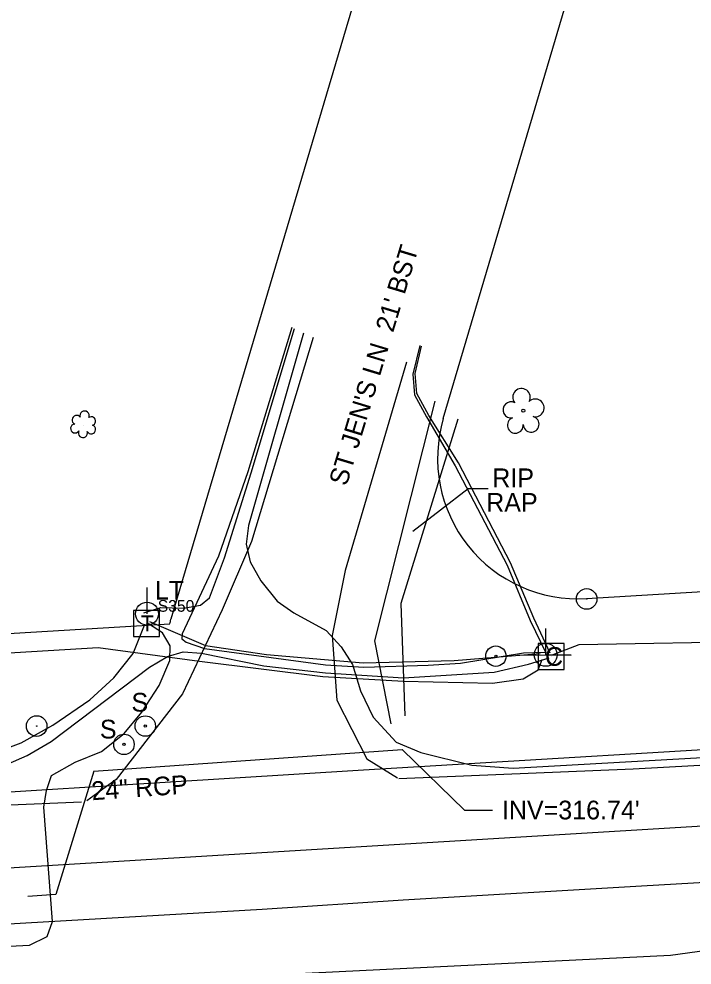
# Model space of a CAD drawing. Extents: x 2110969 to 2113691, y 670003 to 672285.
# Drawn here: x 2112343.6 to 2112487.4, y 670466.5 to 670668.7 of the extents above; entities that cross this region are included whole.
import ezdxf

# ---------------------------------------------------------------- set-up
doc = ezdxf.new("R2010")
doc.units = 0
for name, color, linetype in [('Default', 7, 'Continuous'), ('Exist Horizontal Alignment', 7, 'Continuous'), ('Exist Other Culture Anchor (Guy Wire) CELL', 7, 'Continuous'), ('Exist Other Culture Area Outline', 7, 'Continuous'), ('Exist Other Culture Area Outline Leader', 7, 'Continuous'), ('Exist Other Culture Area Outline Text', 7, 'Continuous'), ('Exist Other Culture Sign Text', 7, 'Continuous'), ('Exist Property Iron Pin CELL', 7, 'Continuous'), ('Exist Right of Way Line', 7, 'Continuous'), ('Exist Right of Way Symbol CELL', 7, 'Continuous'), ('Exist Roads EOP', 7, 'Continuous'), ('Exist Roads EOP Text', 7, 'Continuous'), ('Exist Structure Minor Pipes RCP 24 Inch', 7, 'Continuous'), ('Exist Structure Minor Pipes RCP 24 Inch Invert', 7, 'Continuous'), ('Exist Structure Minor Pipes RCP 24 Inch Leader', 7, 'Continuous'), ('Exist Structure Minor Pipes RCP 24 Inch Text', 7, 'Continuous'), ('Exist Utilities Power Joint Use Telephone CELL', 7, 'Continuous'), ('Exist Utilities Power Pole CELL', 7, 'Continuous'), ('Exist Utilities Power Pole Text', 7, 'Continuous'), ('Exist Utilities Power UG Cable SUE LOS B', 7, 'Continuous'), ('Exist Utilities Telephone Pedestal CELL', 7, 'Continuous'), ('Exist Utilities Telephone Pedestal Cogo Number', 7, 'Continuous'), ('Exist Utilities Telephone UG Cable SUE LOS B', 7, 'Continuous'), ('Exist Utilities Telephone UG FO SUE LOS B', 7, 'Continuous'), ('Exist Utilities TV Pedestal CELL', 7, 'Continuous'), ('Exist Utilities TV UG Cable SUE LOS B', 7, 'Continuous'), ('Exist Utilities TV UG FO Cable SUE LOS B', 7, 'Continuous'), ('Exist Utilities Water UG Line SUE LOS B', 7, 'Continuous'), ('Exist Vegetation Shrub CELL', 7, 'Continuous'), ('Exist Vegetation Tree CELL', 7, 'Continuous')]:
    doc.layers.add(name, color=color, linetype=linetype)

msp = doc.modelspace()

# ---------------------------------------------------------------- linework, layer by layer
at = {"layer": 'Default'}
for centre, radius in [((2112370.63, 670517.59), 2.18), ((2112366.07, 670513.67), 2.18), ((2112370.63, 670517.59), 0.24), ((2112366.07, 670513.67), 0.24)]:
    msp.add_circle(centre, radius, dxfattribs=at)
at = {"layer": 'Exist Horizontal Alignment'}
msp.add_line((2111597.13, 670442.15), (2113362.13, 670549.12), dxfattribs=at)
at = {"layer": 'Exist Other Culture Anchor (Guy Wire) CELL'}
for radius in [2.18, 0.24]:
    msp.add_circle((2112445.52, 670532.52), radius, dxfattribs=at)
at = {"layer": 'Exist Other Culture Area Outline'}
for points in [[(2112423.12, 670518.08), (2112419.67, 670535.82), (2112432.56, 670586.99)], [(2112437.41, 670583.17), (2112425.19, 670543.74), (2112426.08, 670519.76)]]:
    msp.add_lwpolyline(points, dxfattribs=at)
at = {"layer": 'Exist Other Culture Area Outline Leader'}
msp.add_lwpolyline([(2112427.79, 670559.25), (2112439.58, 670568.31), (2112443.89, 670568.31)], dxfattribs=at)
at = {"layer": 'Exist Property Iron Pin CELL'}
for centre, radius in [((2112464.92, 670544.74), 2.2), ((2112464.92, 670544.74), 0.0707), ((2112347.42, 670517.58), 2.2), ((2112347.42, 670517.58), 2.2), ((2112347.42, 670517.58), 0.0707), ((2112347.42, 670517.58), 0.0707)]:
    msp.add_circle(centre, radius, dxfattribs=at)
at = {"layer": 'Exist Right of Way Line'}
for p, q in [((2112434.29, 670583.29), (2112486.67, 670760.31)), ((2112433.78, 670735.06), (2112376.09, 670540.39)), ((2112464.87, 670544.84), (2112636.48, 670555.24)), ((2112002.21, 670516.79), (2112375.84, 670539.44))]:
    msp.add_line(p, q, dxfattribs=at)
msp.add_arc((2112346.97, 670547.58), 30, 344.2535, 346.1413, dxfattribs=at)
at = {"layer": 'Exist Right of Way Symbol CELL'}
msp.add_arc((2112463.06, 670574.78), 30, 163.5164, 273.4682, dxfattribs=at)
at = {"layer": 'Exist Roads EOP'}
for points in [[(2112406.52, 670600.58), (2112393.34, 670557), (2112387.02, 670542.43), (2112378.59, 670524.48), (2112364.4, 670506.13), (2112358.11, 670501.61)], [(2112426.44, 670595.36), (2112413.3, 670550.81), (2112410.52, 670536.95), (2112411.52, 670523.08), (2112417.92, 670510.58), (2112424.52, 670506.54)], [(2112424.8, 670506.36), (2112474.87, 670508.43), (2112528, 670511.35), (2112576.77, 670514.15), (2112631.06, 670517.43), (2112688.93, 670521.02)], [(2112176.4, 670489.41), (2112242.12, 670493.63), (2112288.77, 670496.68), (2112321.51, 670499.72), (2112322.2, 670500.39), (2112339.25, 670501.32), (2112340.12, 670500.67), (2112356.98, 670501.39)], [(2112239.79, 670466.76), (2112249.04, 670469.51), (2112290.21, 670472.2), (2112340.18, 670475.23), (2112395.57, 670478.46), (2112425.73, 670480.47), (2112476.62, 670483.47), (2112528.49, 670486.45), (2112578.55, 670489.44), (2112632.17, 670492.66), (2112690.33, 670496.03), (2112733.41, 670498.51), (2112776.92, 670500.99)]]:
    msp.add_lwpolyline(points, dxfattribs=at)
at = {"layer": 'Exist Structure Minor Pipes RCP 24 Inch'}
msp.add_line((2112359.62, 670507.93), (2112425.48, 670512.56), dxfattribs=at)
at = {"layer": 'Exist Structure Minor Pipes RCP 24 Inch Leader'}
for points in [[(2112425.48, 670512.56), (2112438.81, 670499.64), (2112444.81, 670499.64)], [(2112359.62, 670507.93), (2112351.52, 670481.56), (2112345.53, 670481.19)]]:
    msp.add_lwpolyline(points, dxfattribs=at)
at = {"layer": 'Exist Utilities Power Joint Use Telephone CELL'}
msp.add_line((2112456.17, 670532.79), (2112456.17, 670532.79), dxfattribs=at)
msp.add_lwpolyline([(2112450.23, 670532.79), (2112461.57, 670532.75), (2112456.17, 670532.77), (2112456.17, 670538.41)], dxfattribs=at)
msp.add_circle((2112456.17, 670532.8), 2.45, dxfattribs=at)
at = {"layer": 'Exist Utilities Power Pole CELL'}
for q in [(2112370.99, 670547.22), (2112370.99, 670541.59)]:
    msp.add_line((2112370.99, 670541.59), q, dxfattribs=at)
msp.add_circle((2112370.99, 670541.59), 2.45, dxfattribs=at)
at = {"layer": 'Exist Utilities Power UG Cable SUE LOS B'}
for points in [[(2112370.34, 670541.77), (2112373.96, 670542.89), (2112378.76, 670542.74), (2112382.42, 670543.39), (2112384.33, 670545), (2112387.53, 670553.53), (2112393.23, 670571.68), (2112402.5, 670602.53)], [(2112370.34, 670541.77), (2112373.96, 670542.89), (2112378.76, 670542.74), (2112382.42, 670543.39), (2112384.33, 670545), (2112387.53, 670553.53), (2112393.23, 670571.68), (2112402.5, 670602.53)], [(2112401.94, 670602.73), (2112392.55, 670571.92), (2112386.23, 670553.9), (2112378.48, 670537.29), (2112378.4, 670536.19), (2112379.38, 670535.53), (2112383.28, 670534.17), (2112409.09, 670530.63), (2112417.28, 670530.14), (2112431.07, 670530.56), (2112437.99, 670530.99), (2112451.4, 670533.2), (2112455.98, 670533.35)], [(2112401.94, 670602.73), (2112392.55, 670571.92), (2112386.23, 670553.9), (2112378.48, 670537.29), (2112378.4, 670536.19), (2112379.38, 670535.53), (2112383.28, 670534.17), (2112409.09, 670530.63), (2112417.28, 670530.14), (2112431.07, 670530.56), (2112437.99, 670530.99), (2112451.4, 670533.2), (2112455.98, 670533.35)], [(2112429.25, 670598.93), (2112427.81, 670592.76), (2112428.12, 670588.34), (2112430.72, 670583.62), (2112436.81, 670573.15), (2112447.91, 670551.93), (2112452.85, 670540.14), (2112456.2, 670533.23)], [(2112429.25, 670598.93), (2112427.81, 670592.76), (2112428.12, 670588.34), (2112430.72, 670583.62), (2112436.81, 670573.15), (2112447.91, 670551.93), (2112452.85, 670540.14), (2112456.2, 670533.23)]]:
    msp.add_lwpolyline(points, dxfattribs=at)
at = {"layer": 'Exist Utilities Telephone Pedestal CELL'}
msp.add_line((2112370.79, 670539.51), (2112370.79, 670539.51), dxfattribs=at)
msp.add_line((2112370.79, 670539.51), (2112370.79, 670539.51), dxfattribs=at)
msp.add_lwpolyline([(2112368.07, 670536.69), (2112373.66, 670536.69), (2112373.66, 670542.28), (2112368.07, 670542.28), (2112368.07, 670536.69)], dxfattribs=at)
msp.add_lwpolyline([(2112368.07, 670536.69), (2112373.66, 670536.69), (2112373.66, 670542.28), (2112368.07, 670542.28), (2112368.07, 670536.69)], dxfattribs=at)
at = {"layer": 'Exist Utilities Telephone UG Cable SUE LOS B'}
for points in [[(2112404.42, 670601.5), (2112392.64, 670560.41), (2112392.2, 670556.46), (2112393.02, 670552.68), (2112395.3, 670548.58), (2112398.79, 670544.3), (2112402.34, 670541.77), (2112409.23, 670538.01), (2112412.45, 670534.52), (2112414.89, 670530.7), (2112416.63, 670525.08), (2112419.28, 670519.5), (2112424.23, 670514.15), (2112429.5, 670511.95), (2112440.36, 670509.2), (2112449.21, 670508.58), (2112498.52, 670511.36)], [(2112404.42, 670601.5), (2112392.64, 670560.41), (2112392.2, 670556.46), (2112393.02, 670552.68), (2112395.3, 670548.58), (2112398.79, 670544.3), (2112402.34, 670541.77), (2112409.23, 670538.01), (2112412.45, 670534.52), (2112414.89, 670530.7), (2112416.63, 670525.08), (2112419.28, 670519.5), (2112424.23, 670514.15), (2112429.5, 670511.95), (2112440.36, 670509.2), (2112449.21, 670508.58), (2112498.52, 670511.36)], [(2112125.8, 670505.88), (2112151.42, 670507.16), (2112167.82, 670506.07), (2112175.89, 670503.95), (2112185.08, 670501.15), (2112202.64, 670498.92), (2112224.06, 670500.86), (2112249.24, 670503.38), (2112272.81, 670505.79), (2112322.5, 670509.71), (2112334.68, 670510.5), (2112344.08, 670514.03), (2112350.84, 670517.78), (2112358.78, 670523.19), (2112363.87, 670527.87), (2112368.03, 670533.1), (2112370.46, 670539.12)], [(2112125.8, 670505.88), (2112151.42, 670507.16), (2112167.82, 670506.07), (2112175.89, 670503.95), (2112185.08, 670501.15), (2112202.64, 670498.92), (2112224.06, 670500.86), (2112249.24, 670503.38), (2112272.81, 670505.79), (2112322.5, 670509.71), (2112334.68, 670510.5), (2112344.08, 670514.03), (2112350.84, 670517.78), (2112358.78, 670523.19), (2112363.87, 670527.87), (2112368.03, 670533.1), (2112370.46, 670539.12)], [(2112269.39, 670466.11), (2112308.69, 670468.9), (2112345.88, 670470.75), (2112349.64, 670472.64), (2112350.81, 670475.84), (2112348.97, 670500.24), (2112349.51, 670503.8), (2112350.6, 670506.99), (2112355.66, 670509.89), (2112361.29, 670512.16), (2112366.08, 670515.96), (2112369.85, 670520.57), (2112373.6, 670526.25), (2112375.89, 670531.57), (2112375.94, 670534.69), (2112374.31, 670537.47), (2112371.32, 670539.46)], [(2112269.39, 670466.11), (2112308.69, 670468.9), (2112345.88, 670470.75), (2112349.64, 670472.64), (2112350.81, 670475.84), (2112348.97, 670500.24), (2112349.51, 670503.8), (2112350.6, 670506.99), (2112355.66, 670509.89), (2112361.29, 670512.16), (2112366.08, 670515.96), (2112369.85, 670520.57), (2112373.6, 670526.25), (2112375.89, 670531.57), (2112375.94, 670534.69), (2112374.31, 670537.47), (2112371.32, 670539.46)], [(2112371.52, 670539.93), (2112380.52, 670536.07), (2112383.49, 670534.77), (2112396.55, 670532.85), (2112417.17, 670531.11), (2112436.61, 670531.57), (2112454.98, 670533.12)], [(2112371.52, 670539.93), (2112380.52, 670536.07), (2112383.49, 670534.77), (2112396.55, 670532.85), (2112417.17, 670531.11), (2112436.61, 670531.57), (2112454.98, 670533.12)]]:
    msp.add_lwpolyline(points, dxfattribs=at)
at = {"layer": 'Exist Utilities Telephone UG FO SUE LOS B'}
msp.add_lwpolyline([(2111579.85, 670418.18), (2111631.45, 670423.41), (2111740.38, 670432.81), (2111885.62, 670444.53), (2111926.38, 670441.18), (2111977.11, 670441.9), (2112063.2, 670445.72), (2112109.68, 670453.08), (2112138.77, 670453.18), (2112237, 670457.87), (2112306.5, 670460.33), (2112380.27, 670463.6), (2112482.83, 670468.65), (2112529.94, 670475.11), (2112581.42, 670479.39), (2112613.55, 670486.14), (2112667.68, 670491.25), (2112816.71, 670501.11)], dxfattribs=at)
msp.add_lwpolyline([(2111579.85, 670418.18), (2111631.45, 670423.41), (2111740.38, 670432.81), (2111885.62, 670444.53), (2111926.38, 670441.18), (2111977.11, 670441.9), (2112063.2, 670445.72), (2112109.68, 670453.08), (2112138.77, 670453.18), (2112237, 670457.87), (2112306.5, 670460.33), (2112380.27, 670463.6), (2112482.83, 670468.65), (2112529.94, 670475.11), (2112581.42, 670479.39), (2112613.55, 670486.14), (2112667.68, 670491.25), (2112816.71, 670501.11)], dxfattribs=at)
at = {"layer": 'Exist Utilities TV Pedestal CELL'}
msp.add_line((2112457.32, 670532.45), (2112457.32, 670532.45), dxfattribs=at)
msp.add_line((2112457.32, 670532.45), (2112457.32, 670532.45), dxfattribs=at)
msp.add_lwpolyline([(2112454.54, 670529.68), (2112460.09, 670529.68), (2112460.09, 670535.23), (2112454.54, 670535.23), (2112454.54, 670529.68)], dxfattribs=at)
msp.add_lwpolyline([(2112454.54, 670529.68), (2112460.09, 670529.68), (2112460.09, 670535.23), (2112454.54, 670535.23), (2112454.54, 670529.68)], dxfattribs=at)
at = {"layer": 'Exist Utilities TV UG Cable SUE LOS B'}
for points in [[(2112457.14, 670533.15), (2112453.6, 670540.6), (2112448.62, 670552.49), (2112437.56, 670573.8), (2112431.2, 670583.96), (2112428.63, 670588.61), (2112428.28, 670592.91), (2112429.65, 670598.77)], [(2112457.14, 670533.15), (2112453.6, 670540.6), (2112448.62, 670552.49), (2112437.56, 670573.8), (2112431.2, 670583.96), (2112428.63, 670588.61), (2112428.28, 670592.91), (2112429.65, 670598.77)], [(2112457.79, 670532.84), (2112463.34, 670534.99), (2112503.28, 670535.72), (2112536.36, 670537.77), (2112607.48, 670541.98), (2112636.29, 670544.75), (2112653.86, 670545.32), (2112661.64, 670544.86)], [(2112457.79, 670532.84), (2112463.34, 670534.99), (2112503.28, 670535.72), (2112536.36, 670537.77), (2112607.48, 670541.98), (2112636.29, 670544.75), (2112653.86, 670545.32), (2112661.64, 670544.86)], [(2112188.85, 670513.35), (2112191.54, 670508.61), (2112194.04, 670505.15), (2112197.61, 670502.68), (2112202.27, 670501.48), (2112208.12, 670501.36), (2112249.19, 670503.68), (2112272.77, 670504.74), (2112322.55, 670508.19), (2112335.1, 670508.45), (2112341.36, 670509.49), (2112345.38, 670511.27), (2112350.51, 670514.31), (2112371.55, 670530.16), (2112375.39, 670532.48), (2112378.7, 670533.44), (2112382.64, 670533.13), (2112395.98, 670530.48), (2112409.14, 670528.93), (2112425.81, 670527.86), (2112445.18, 670529.08), (2112452.46, 670530.8), (2112456.91, 670532.18)], [(2112188.85, 670513.35), (2112191.54, 670508.61), (2112194.04, 670505.15), (2112197.61, 670502.68), (2112202.27, 670501.48), (2112208.12, 670501.36), (2112249.19, 670503.68), (2112272.77, 670504.74), (2112322.55, 670508.19), (2112335.1, 670508.45), (2112341.36, 670509.49), (2112345.38, 670511.27), (2112350.51, 670514.31), (2112371.55, 670530.16), (2112375.39, 670532.48), (2112378.7, 670533.44), (2112382.64, 670533.13), (2112395.98, 670530.48), (2112409.14, 670528.93), (2112425.81, 670527.86), (2112445.18, 670529.08), (2112452.46, 670530.8), (2112456.91, 670532.18)]]:
    msp.add_lwpolyline(points, dxfattribs=at)
at = {"layer": 'Exist Utilities TV UG FO Cable SUE LOS B'}
msp.add_lwpolyline([(2111936.85, 670495.19), (2111942.8, 670493.29), (2111948.9, 670492.04), (2111960.42, 670490.85), (2111972.12, 670490.75), (2111991.92, 670492.74), (2112005.47, 670495.02), (2112045.67, 670498.63), (2112084.03, 670500.97), (2112127.19, 670501.84), (2112167.43, 670504.61), (2112208.93, 670510.16), (2112249.37, 670516.92), (2112286.91, 670525.52), (2112332.02, 670532.67), (2112360.55, 670534.37), (2112382.17, 670531.42), (2112408.52, 670528.19), (2112425.77, 670527.19), (2112444.78, 670526.78), (2112451.38, 670527.68), (2112454.55, 670529.63), (2112455.41, 670531.77)], dxfattribs=at)
msp.add_lwpolyline([(2111936.85, 670495.19), (2111942.8, 670493.29), (2111948.9, 670492.04), (2111960.42, 670490.85), (2111972.12, 670490.75), (2111991.92, 670492.74), (2112005.47, 670495.02), (2112045.67, 670498.63), (2112084.03, 670500.97), (2112127.19, 670501.84), (2112167.43, 670504.61), (2112208.93, 670510.16), (2112249.37, 670516.92), (2112286.91, 670525.52), (2112332.02, 670532.67), (2112360.55, 670534.37), (2112382.17, 670531.42), (2112408.52, 670528.19), (2112425.77, 670527.19), (2112444.78, 670526.78), (2112451.38, 670527.68), (2112454.55, 670529.63), (2112455.41, 670531.77)], dxfattribs=at)
at = {"layer": 'Exist Utilities Water UG Line SUE LOS B'}
msp.add_lwpolyline([(2112063.12, 670452.82), (2112061.08, 670490.25), (2112149, 670492.87), (2112291.17, 670500.39), (2112417.24, 670508.2), (2112519.46, 670514.32), (2112696.23, 670524.3), (2112788.03, 670530.3), (2112902.5, 670537.78), (2113013.6, 670544.43), (2113214.88, 670557.36), (2113313.23, 670563.26)], dxfattribs=at)
msp.add_lwpolyline([(2112063.12, 670452.82), (2112061.08, 670490.25), (2112149, 670492.87), (2112291.17, 670500.39), (2112417.24, 670508.2), (2112519.46, 670514.32), (2112696.23, 670524.3), (2112788.03, 670530.3), (2112902.5, 670537.78), (2113013.6, 670544.43), (2113214.88, 670557.36), (2113313.23, 670563.26)], dxfattribs=at)
at = {"layer": 'Exist Vegetation Shrub CELL'}
msp.add_line((2112357.42, 670581.87), (2112357.42, 670581.87), dxfattribs=at)
for centre, radius, start, end in [((2112357.65, 670583.91), 0.99, 334.8391, 200.4717), ((2112355.94, 670583), 0.968, 35.8908, 245.4216), ((2112359.09, 670582.74), 0.929, 284.4567, 126.0861), ((2112355.62, 670581.17), 0.955, 95.1099, 327.9534), ((2112357.29, 670580.19), 0.984, 151.2797, 21.387), ((2112359.06, 670580.94), 0.937, 204.9913, 73.4601)]:
    msp.add_arc(centre, radius, start, end, dxfattribs=at)
at = {"layer": 'Exist Vegetation Tree CELL'}
msp.add_line((2112451.38, 670584.97), (2112451.38, 670584.97), dxfattribs=at)
msp.add_circle((2112451.38, 670584.97), 0.326, dxfattribs=at)
for centre, radius, start, end in [((2112450.99, 670587.85), 1.86, 330.1651, 219.7134), ((2112448.77, 670585.13), 1.73, 62.6636, 279.3457), ((2112453.93, 670585.56), 1.9, 257.1011, 134.1999), ((2112449.67, 670581.85), 1.69, 111.5671, 6.231), ((2112453.05, 670582.07), 1.7, 181.2822, 74.56)]:
    msp.add_arc(centre, radius, start, end, dxfattribs=at)

# ---------------------------------------------------------------- texts
at = {"layer": 'Exist Other Culture Area Outline Text'}
for s, p in [('RIP', (2112444.75, 670568.62)), ('RAP', (2112443.45, 670563.37))]:
    msp.add_text(s, height=4, dxfattribs=at).set_placement(p)
at = {"layer": 'Exist Other Culture Sign Text'}
for p in [(2112367.67, 670520.67), (2112360.92, 670514.93)]:
    msp.add_text('S', height=4, dxfattribs=at).set_placement(p)
at = {"layer": 'Exist Roads EOP Text'}
msp.add_text("ST JEN'S LN  21' BST", height=4, rotation=73.1644, dxfattribs=at).set_placement((2112413.62, 670568.68))
at = {"layer": 'Exist Structure Minor Pipes RCP 24 Inch Invert'}
msp.add_text("INV=316.74'", height=4, dxfattribs=at).set_placement((2112446.81, 670497.64))
at = {"layer": 'Exist Structure Minor Pipes RCP 24 Inch Text'}
msp.add_text('24" RCP', height=4, rotation=4.0183, dxfattribs=at).set_placement((2112359.25, 670501.72))
at = {"layer": 'Exist Utilities Power Pole Text'}
msp.add_text('LT', height=4, dxfattribs=at).set_placement((2112372.65, 670544.61))
at = {"layer": 'Exist Utilities Telephone Pedestal CELL'}
msp.add_text('T', height=3.42, dxfattribs=at).set_placement((2112369.66, 670537.8))
msp.add_text('T', height=3.42, dxfattribs=at).set_placement((2112369.66, 670537.8))
at = {"layer": 'Exist Utilities Telephone Pedestal Cogo Number'}
msp.add_text('S350', height=2.5, dxfattribs=at).set_placement((2112373.29, 670542.01))
at = {"layer": 'Exist Utilities TV Pedestal CELL'}
msp.add_text('C', height=4, dxfattribs=at).set_placement((2112456.01, 670530.45))
msp.add_text('C', height=4, dxfattribs=at).set_placement((2112456.01, 670530.45))

doc.saveas('drawing.dxf')
